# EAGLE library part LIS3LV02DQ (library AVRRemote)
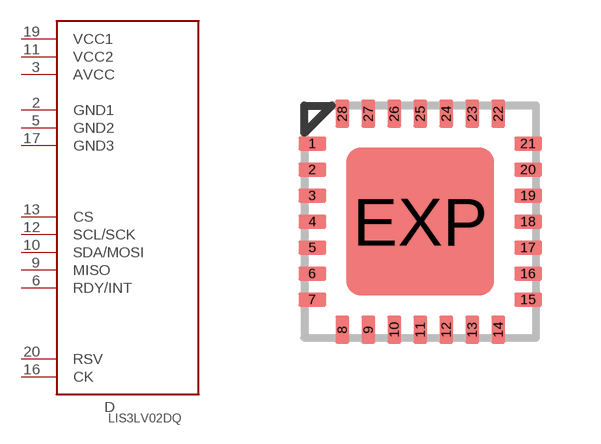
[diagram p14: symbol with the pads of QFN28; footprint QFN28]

Designator prefix D

## LIS3LV02DQ  [QFN28]
2  GND1  sup
3  AVCC  sup
5  GND2  sup
6  RDY/INT
9  MISO
10  SDA/MOSI
11  VCC2  sup
12  SCL/SCK
13  CS
16  CK
17  GND3  sup
19  VCC1  sup
20  RSV

## Footprint QFN28 (pad centres in mm)
QFN28-ML_6X6MM Source: http://www.microchip.com .. 39637a.pdf
smd 0.7 x 0.35: 1 -2.7,1.95; 2 -2.7,1.3; 3 -2.7,0.65; 4 -2.7,0; 5 -2.7,-0.65; 6 -2.7,-1.3; 7 -2.7,-1.95; 15 2.7,-1.95; 16 2.7,-1.3; 17 2.7,-0.65; 18 2.7,0; 19 2.7,0.65; 20 2.7,1.3; 21 2.7,1.95
smd 0.35 x 0.7: 8 -1.95,-2.7; 9 -1.3,-2.7; 10 -0.65,-2.7; 11 0,-2.7; 12 0.65,-2.7; 13 1.3,-2.7; 14 1.95,-2.7; 22 1.95,2.7; 23 1.3,2.7; 24 0.65,2.7; 25 0,2.7; 26 -0.65,2.7; 27 -1.3,2.7; 28 -1.95,2.7
smd 3.7 x 3.7: EXP 0,0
